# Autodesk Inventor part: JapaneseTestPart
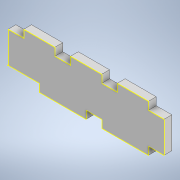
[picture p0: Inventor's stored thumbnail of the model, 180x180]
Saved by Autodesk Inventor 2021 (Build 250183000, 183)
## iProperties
Created: 2026-10
Part Number: JapaneseTestPart
Material: Generic
Document SubType Name: Modeling
Designer: hp
Density: 1 g/cm^3
Appearance: Default
Author: hp
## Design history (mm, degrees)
sketch "Sketch1" dims "d15" = 10
  geometry: L1 (0, 0)-(100, 0); L2 (100, 0)-(100, 20); L3 (100, 20)-(0, 20); L4 (0, 20)-(0, 0); L5 (90, -5)-(90, 0); L6 (90, 0)-(60, 0); L7 (60, 0)-(60, -5); L8 (60, -5)-(90, -5); L9 (50, -5)-(50, 0); L10 (20, 0)-(20, -5); L11 (20, -5)-(50, -5); L12 (50, 0)-(20, 0); L13 (60, 20)-(60, 25); L14 (70, 25)-(70, 20); L15 (70, 20)-(90, 20); L16 (90, 25)-(70, 25); L17 (90, 20)-(90, 25); L18 (30, 20)-(30, 25); L19 (30, 25)-(10, 25); L20 (10, 20)-(30, 20); L21 (10, 25)-(10, 20); L22 (40, 20)-(60, 20); L23 (60, 25)-(40, 25); L24 (40, 25)-(40, 20); 12 further points
  constraints: 48 end point, 8 parallel, 5 horizontal, 4 perpendicular, 2 collinear, 2 midpoint, 2 point on line, 15 other
  dimensions: "d0" = 100 distance of L3.end L2.end; "d1" = 20 distance of L1.end L2.end; "d2" = 30 distance of L5.start L7.end; "d3" = 5 distance of L7.end L6.end; "d4" = 30 distance of L9.start L10.end; "d5" = 5 distance of L10.end L10.start; "d6" = 10 distance between parallel lines of L9 L7; "d7" = 10 distance from line of L5 L1.end; "d12" = 20 distance of L15.end L14.end; "d13" = 5 distance of L14.end L14.start; "d14" = 30 distance of L14.end L22.start; "d16" = 10 distance from line of L2.end L17
extrude "Extrusion1" new body sketch "Sketch1" distance "d17" = 5; taper "d18" = 0 deg
sketch "Sketch2"
  geometry: L1 (10, 25)-(10, 20) reference; L2 (10, 20)-(0, 20) reference; L3 (0, 20)-(0, 0) reference; L4 (0, 0)-(20, 0) reference; L5 (20, 0)-(20, -5) reference; L6 (20, -5)-(50, -5) reference; L7 (50, -5)-(50, 0) reference; L8 (50, 0)-(60, 0) reference; L9 (60, 0)-(60, -5) reference; L10 (60, -5)-(90, -5) reference; L11 (90, -5)-(90, 0) reference; L12 (90, 0)-(100, 0) reference; L13 (100, 0)-(100, 20) reference; L14 (100, 20)-(90, 20) reference; L15 (90, 20)-(90, 25) reference; L16 (90, 25)-(70, 25) reference; L17 (70, 25)-(70, 20) reference; L18 (70, 20)-(60, 20) reference; L19 (60, 20)-(60, 25) reference; L20 (60, 25)-(40, 25) reference; L21 (40, 25)-(40, 20) reference; L22 (40, 20)-(30, 20) reference; L23 (30, 20)-(30, 25) reference; L24 (30, 25)-(10, 25) reference; 1 further point
  node "Projected Loop1"
body "Solid1"
